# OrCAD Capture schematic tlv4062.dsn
size A
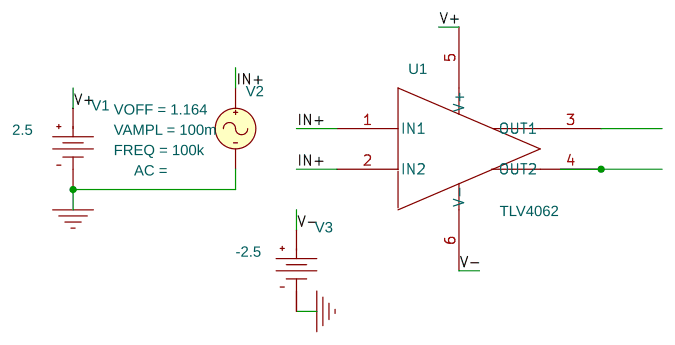
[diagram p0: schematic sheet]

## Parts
U1  TLV4062
V1  VDC
V2  VSIN
V3  VDC

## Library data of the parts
U1 = TLV4062_1
V1 = VDC: DC: 2.5
V2 = VSIN: FREQ: 100k; VAMPL: 100m; VOFF: 1.164
V3 = VDC: DC: -2.5

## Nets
0: V1.1(-) V2.2(-) V3.1(-)
IN+: U1.1(IN1) U1.2(IN2) V2.1(+)
V+: U1.5(V+) V1.0(+)
V-: U1.6(V-) V3.0(+)

Not connected (* = marked no-connect by the designer): U1 3(OUT1) 4(OUT2)
